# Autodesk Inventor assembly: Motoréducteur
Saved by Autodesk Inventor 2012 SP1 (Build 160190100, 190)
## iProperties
Created: 2014-12
Part Number: Motoréducteur
Document SubType Name: Assembly
Designer: Bruno
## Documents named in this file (4)
- D:\Cours\Systèmes\secateur-hydrogene-Pragma\Documentation\Dossier technique Infaco F3005\Solidworks\Composants importés\F3005\Motoréducteur.iam
- D:\Cours\Systèmes\secateur-hydrogene-Pragma\Documentation\Dossier technique Infaco F3005\Solidworks\Composants importés\F3005\Bobine moteur.ipt
- D:\Cours\Systèmes\secateur-hydrogene-Pragma\Documentation\Dossier technique Infaco F3005\Solidworks\Composants importés\F3005\Roulement reducteur.ipt
- D:\Cours\Systèmes\secateur-hydrogene-Pragma\Documentation\Dossier technique Infaco F3005\Solidworks\Composants importés\F3005\Tube moteur.ipt
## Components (3 placed, 3 different names)
1. Bobine moteur:1
2. Roulement reducteur:1
3. Tube moteur:1
